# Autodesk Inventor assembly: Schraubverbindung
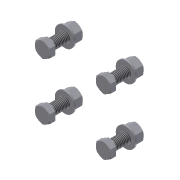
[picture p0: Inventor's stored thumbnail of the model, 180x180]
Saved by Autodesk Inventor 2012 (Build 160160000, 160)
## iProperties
Company: CAD-Verlag
Created: 2004-12
Part Number: Schraubverbindung
Document SubType Name: Assembly
Designer: jukr
Manufacturer: Standard
Standards Organization: Custom
Author: Jürgen Kronas
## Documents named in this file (4)
- C:\Daten Vault 2012 Inventor\Kapitel 6\6.4\Rollenbahn\Bibliotheken\Schraubverbindung.iam
- C:\Daten Vault 2012 Inventor\Kapitel 6\6.4\Rollenbahn\Bibliotheken\I4017A000Q9FLB_MIR.ipt
- C:\Daten Vault 2012 Inventor\Kapitel 6\6.4\Rollenbahn\Bibliotheken\D125_2000RI1XB_MIR.ipt
- C:\Daten Vault 2012 Inventor\Kapitel 6\6.4\Rollenbahn\Bibliotheken\I4032000YBW6B_MIR.ipt
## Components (12 placed, 3 different names)
1. I4017A000Q9FLB_MIR:1
2. D125_2000RI1XB_MIR:1
3. I4032000YBW6B_MIR:1
4. I4017A000Q9FLB_MIR:2
5. D125_2000RI1XB_MIR:2
6. I4032000YBW6B_MIR:2
7. I4017A000Q9FLB_MIR:3
8. D125_2000RI1XB_MIR:3
9. I4032000YBW6B_MIR:3
10. I4017A000Q9FLB_MIR:4
11. D125_2000RI1XB_MIR:4
12. I4032000YBW6B_MIR:4
